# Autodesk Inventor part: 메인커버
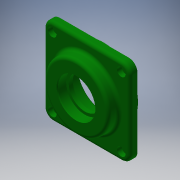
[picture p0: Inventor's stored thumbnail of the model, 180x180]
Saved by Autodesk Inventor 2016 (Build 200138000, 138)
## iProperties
Created: 2018-09
Part Number: 메인커버
Material: 알루미늄 6061
Document SubType Name: Modeling
Designer: mduedu
Density: 2.71 g/cm^3
Mass: 178.463 g
Surface Area: 197.883 cm^2
Volume: 65.8536 cm^3
Appearance: 진녹색
Author: mduedu
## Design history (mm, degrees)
sketch "스케치1"
  geometry: L1 (-40, -40)-(40, -40); L2 (40, -40)-(40, 40); L3 (40, 40)-(-40, 40); L4 (-40, 40)-(-40, -40); L5 (-40, -40)-(40, 40); L6 (40, -40)-(-40, 40); 1 further point
  constraints: 12 end point, 2 midpoint, 2 parallel, 1 horizontal, 1 perpendicular
  dimensions: "d0" = 80 distance of L3.end L2.end; "d1" = 80 distance of L2.end L1.end
extrude "돌출1" new body sketch "스케치1" distance "d2" = 7; taper "d3" = 0 deg
sketch "스케치2"
  geometry: C1 r 30 at (0, 0); 1 further point
  constraints: 1 centre point, 1 coincident
  dimensions: "d4" = 60 diameter of C1
extrude "돌출2" join sketch "스케치2" distance "d5" = 10; taper "d6" = 0 deg
sketch "스케치3"
  geometry: C1 r 32.5 at (0, 0); 1 further point
  constraints: 1 centre point, 1 coincident
  dimensions: "d7" = 65 diameter of C1
extrude "돌출3" join sketch "스케치3" distance "d8" = 9; taper "d9" = 0 deg
sketch "스케치4"
  geometry: L1 (-32.5, -9)-(32.5, -9) reference; L2 (30, 17)-(-30, 17) reference; L3 (0, 17)-(0, -9); L4 (0, -9)-(23.5, -9); L5 (23.5, -9)-(23.5, 5); L6 (23.5, 5)-(0, 5); L7 (0, 5)-(0, -9); L8 (0, 5)-(15, 5); L9 (15, 5)-(15, 8.7); L10 (15, 8.7)-(0, 8.7); L11 (0, 8.7)-(0, 5); L12 (0, 8.7)-(17.5, 8.7); L13 (17.5, 8.7)-(17.5, 17); L14 (17.5, 17)-(0, 17); L15 (0, 17)-(0, 8.7); 1 further point
  constraints: 26 end point, 6 parallel, 3 horizontal, 3 perpendicular, 2 midpoint, 1 point on line
  dimensions: "d10" = 14 distance of L4.end L5.end; "d12" = 8.3 distance of L12.end L13.end; "d13" = 35 diameter of L13 L3; "d14" = 30 diameter of L9 L3; "d15" = 47 diameter of L5 L3
revolve "회전1" sketch "스케치4" stored, may be unused: angle "d16" = 90 deg
fillet "모깎기1" dims "d17" = 8
fillet "모깎기2" dims "d18" = 3
fillet "모깎기3" dims "d19" = 3
chamfer "모따기1" distance "d20" = 0.8; stored, may be unused: second distance "d21" = 2, angle "d22" = 30 deg
chamfer "모따기2" distance "d23" = 1; stored, may be unused: second distance "d24" = 2, angle "d25" = 30 deg
fillet "모깎기4" dims "d26" = 0.3
sketch "스케치5"
  geometry: A1 r 8 centre (-32, 32) between (-32, 40) and (-40, 32) reference; A2 r 8 centre (-32, -32) between (-40, -32) and (-32, -40) reference; A3 r 8 centre (32, -32) between (32, -40) and (40, -32) reference; A4 r 8 centre (32, 32) between (40, 32) and (32, 40) reference; 5 further points
  constraints: 4 coincident
hole "구멍1" sketch "스케치5" at (-32, 32), (32, 32), (32, -32), (-32, -32) diameter "d27" = 4.5; stored, may be unused: countersink angle "d31" = 90 deg, drill point angle "d33" = 118 deg; dims "d28" = 6, "d29" = 8, "d30" = 4.4, "d32" = 8
node "솔리드1"
